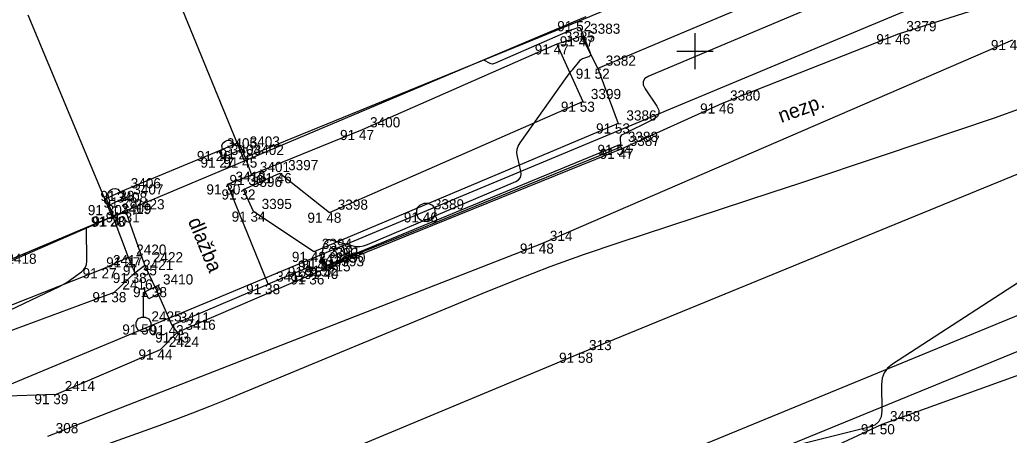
# Model space of a CAD drawing. Extents: x -711081 to -709338, y -1025122 to -1024092.
# Drawn here: x -710543.62 to -710516.33, y -1024835.58 to -1024824.13 of the extents above; entities that cross this region are included whole.
import ezdxf

# ---------------------------------------------------------------- set-up
doc = ezdxf.new("R2010")
doc.units = 0
for name, color, linetype in [('Ex_Minor Contours', 7, 'Continuous'), ('Z_betonova_konstrukce', 7, 'Continuous'), ('Z_body', 7, 'Continuous'), ('Z_body_cisla', 7, 'Continuous'), ('Z_body_vysky_redukovane', 7, 'Continuous'), ('Z_budova', 7, 'Continuous'), ('Z_hektometricka_sit', 7, 'Continuous'), ('Z_hrany_paty', 7, 'Continuous'), ('Z_katastr_hranice', 7, 'Continuous'), ('Z_katastr_hranice_katastralniho_uzemi', 7, 'Continuous'), ('Z_katastr_vnitrni_kresba', 7, 'Continuous'), ('Z_komunikace', 7, 'Continuous'), ('Z_komunikace_osa', 7, 'Continuous'), ('Z_obruba', 7, 'Continuous'), ('Z_ploty', 7, 'Continuous'), ('Z_ploty_znacky', 7, 'Continuous'), ('Z_popisy', 7, 'Continuous'), ('Z_rozhranni', 7, 'Continuous'), ('Z_site_kanalizace_znaky', 7, 'Continuous'), ('Z_site_vo_znaky', 7, 'Continuous'), ('Z_vstupy', 7, 'Continuous'), ('Z_zelen_obvod', 7, 'Continuous'), ('Z_zlabek', 7, 'Continuous')]:
    doc.layers.add(name, color=color, linetype=linetype)

# ---------------------------------------------------------------- blocks, each defined once
blk = doc.blocks.new('POINT_DISPLAY')
blk.add_line((0, 0), (0, 0))
blk = doc.blocks.new('Z216')
for p, q in [((-0.17, 0), (-0.15, 0.1)), ((-0.15, 0.1), (-0.1, 0.15)), ((-0.1, 0.15), (-0.03, 0.17)), ((-0.03, 0.17), (0.03, 0.17)), ((0.03, 0.17), (0.1, 0.15)), ((0.1, 0.15), (0.15, 0.1)), ((0.15, 0.1), (0.17, 0))]:
    blk.add_line(p, q)
blk = doc.blocks.new('Z13')
for p, q in [((0, 0.88), (0.45, 1.1)), ((0, 0.2), (0, 0.88)), ((0.15, 0.7), (0.05, 0.9)), ((0.5, 0.88), (0.15, 0.7)), ((0.4, 1.07), (0.5, 0.88)), ((-0.2, 0.05), (-0.15, 0.15)), ((-0.2, -0.05), (-0.2, 0.05)), ((-0.15, 0.15), (-0.05, 0.2)), ((-0.05, 0.2), (0.05, 0.2)), ((0.05, 0.2), (0.15, 0.15)), ((0.15, 0.15), (0.2, 0.05)), ((0.2, 0.05), (0.2, -0.05)), ((-0.15, -0.15), (-0.2, -0.05)), ((-0.05, -0.2), (-0.15, -0.15)), ((0.05, -0.2), (-0.05, -0.2)), ((0.15, -0.15), (0.05, -0.2)), ((0.2, -0.05), (0.15, -0.15))]:
    blk.add_line(p, q)
blk = doc.blocks.new('Z620')
for p, q in [((-0.25, 0.05), (-0.23, 0.13)), ((-0.25, -0.05), (-0.25, 0.05)), ((-0.23, 0.13), (-0.17, 0.2)), ((-0.17, 0.2), (-0.05, 0.25)), ((-0.05, 0.25), (0.05, 0.25)), ((0.05, 0.25), (0.17, 0.2)), ((0.17, 0.2), (0.23, 0.13)), ((0.23, 0.13), (0.25, 0.05)), ((0.25, 0.05), (0.25, -0.05)), ((-0.2, -0.17), (-0.25, -0.05)), ((-0.13, -0.23), (-0.2, -0.17)), ((-0.05, -0.25), (-0.13, -0.23)), ((0.05, -0.25), (-0.05, -0.25)), ((0.13, -0.23), (0.05, -0.25)), ((0.2, -0.17), (0.13, -0.23)), ((0.25, -0.05), (0.2, -0.17))]:
    blk.add_line(p, q)

msp = doc.modelspace()

# ---------------------------------------------------------------- linework, layer by layer
at = {"layer": 'Ex_Minor Contours'}
for points in [[(-710520.898, -1024823.422), (-710526.271, -1024825.688), (-710526.377, -1024825.752), (-710526.43, -1024825.832), (-710526.429, -1024825.927), (-710526.375, -1024826.039), (-710526.052, -1024826.516), (-710525.997, -1024826.628), (-710525.995, -1024826.727), (-710526.045, -1024826.811), (-710526.148, -1024826.882), (-710527.002, -1024827.306), (-710527.031, -1024827.326), (-710527.051, -1024827.35), (-710527.062, -1024827.38), (-710527.064, -1024827.416), (-710527.052, -1024827.567), (-710527.054, -1024827.602), (-710527.065, -1024827.631), (-710527.086, -1024827.654), (-710527.116, -1024827.672), (-710531.086, -1024829.291), (-710531.492, -1024829.456), (-710531.899, -1024829.621), (-710532.305, -1024829.785), (-710532.713, -1024829.948), (-710535.128, -1024830.914), (-710535.142, -1024830.917), (-710535.155, -1024830.917), (-710535.167, -1024830.912), (-710535.179, -1024830.904), (-710535.223, -1024830.861), (-710535.234, -1024830.85), (-710535.243, -1024830.839), (-710535.252, -1024830.827), (-710535.26, -1024830.814), (-710535.302, -1024830.745), (-710535.304, -1024830.741), (-710535.306, -1024830.736), (-710535.307, -1024830.732), (-710535.309, -1024830.727), (-710535.312, -1024830.708), (-710535.313, -1024830.704), (-710535.313, -1024830.699), (-710535.313, -1024830.694), (-710535.312, -1024830.69), (-710535.229, -1024830.335), (-710535.223, -1024830.316), (-710535.216, -1024830.299), (-710535.206, -1024830.283), (-710535.194, -1024830.268), (-710535.141, -1024830.209), (-710535.127, -1024830.197), (-710535.112, -1024830.19), (-710535.095, -1024830.188), (-710535.077, -1024830.19), (-710534.459, -1024830.36), (-710534.35, -1024830.381), (-710534.243, -1024830.383), (-710534.136, -1024830.366), (-710534.031, -1024830.331), (-710529.942, -1024828.592), (-710529.861, -1024828.543), (-710529.81, -1024828.48), (-710529.79, -1024828.401), (-710529.799, -1024828.307), (-710529.897, -1024827.9), (-710529.911, -1024827.801), (-710529.903, -1024827.705), (-710529.874, -1024827.614), (-710529.824, -1024827.527), (-710528.523, -1024825.702), (-710528.486, -1024825.651), (-710528.448, -1024825.601), (-710528.41, -1024825.552), (-710528.371, -1024825.503), (-710528.178, -1024825.268), (-710528.154, -1024825.242), (-710528.126, -1024825.221), (-710528.096, -1024825.203), (-710528.063, -1024825.19), (-710527.925, -1024825.146), (-710527.896, -1024825.132), (-710527.88, -1024825.113), (-710527.875, -1024825.087), (-710527.882, -1024825.057), (-710528.136, -1024824.405), (-710528.152, -1024824.377), (-710528.173, -1024824.36), (-710528.199, -1024824.355), (-710528.231, -1024824.36), (-710528.369, -1024824.404), (-710528.403, -1024824.415), (-710528.437, -1024824.428), (-710528.471, -1024824.441), (-710528.504, -1024824.455), (-710530.525, -1024825.343), (-710530.555, -1024825.353), (-710530.585, -1024825.355), (-710530.615, -1024825.351), (-710530.645, -1024825.339), (-710530.821, -1024825.244)], [(-710542.524, -1024836.3), (-710539.776, -1024835.318), (-710539.308, -1024835.147), (-710538.843, -1024834.971), (-710538.379, -1024834.789), (-710537.918, -1024834.601), (-710530.868, -1024831.675), (-710529.933, -1024831.298), (-710528.991, -1024830.938), (-710528.042, -1024830.596), (-710527.087, -1024830.273), (-710522.871, -1024828.889), (-710522.103, -1024828.636), (-710521.335, -1024828.381), (-710520.568, -1024828.125), (-710519.802, -1024827.867), (-710516.737, -1024826.833), (-710515.975, -1024826.564)], [(-710546.046, -1024833.16), (-710542.522, -1024831.483), (-710542.44, -1024831.442), (-710542.361, -1024831.398), (-710542.284, -1024831.349), (-710542.21, -1024831.297), (-710541.915, -1024831.08), (-710541.851, -1024831.021), (-710541.806, -1024830.953), (-710541.779, -1024830.876), (-710541.77, -1024830.789), (-710541.779, -1024829.876)], [(-710515.235, -1024830.831), (-710519.555, -1024833.627), (-710519.688, -1024833.737), (-710519.782, -1024833.867), (-710519.838, -1024834.017), (-710519.855, -1024834.189), (-710519.845, -1024834.916), (-710519.865, -1024835.081), (-710519.93, -1024835.211), (-710520.039, -1024835.307), (-710520.193, -1024835.368), (-710525.827, -1024836.766)]]:
    msp.add_lwpolyline(points, dxfattribs=at)
at = {"layer": 'Z_betonova_konstrukce'}
for p, q in [((-710541.05, -1024829.56), (-710540.63, -1024830.68)), ((-710540.69, -1024829.44), (-710541.04, -1024829.55)), ((-710540.17, -1024830.9), (-710540.69, -1024829.44)), ((-710540.63, -1024830.68), (-710540.45, -1024831.11)), ((-710540.45, -1024831.11), (-710540.17, -1024830.9))]:
    msp.add_line(p, q, dxfattribs=at)
at = {"layer": 'Z_budova'}
for p, q in [((-710521.51, -1024821.36), (-710528.19, -1024824.17)), ((-710528.19, -1024824.17), (-710537.4, -1024827.93)), ((-710537.6, -1024827.52), (-710537.5, -1024827.7)), ((-710537.4, -1024827.93), (-710537.5, -1024827.7)), ((-710541.24, -1024829.06), (-710541.16, -1024829.24)), ((-710541.16, -1024829.24), (-710541.04, -1024829.55)), ((-710544.21, -1024830.93), (-710541.05, -1024829.56)), ((-710541.05, -1024829.56), (-710541.04, -1024829.55))]:
    msp.add_line(p, q, dxfattribs=at)
at = {"layer": 'Z_hektometricka_sit'}
for p, q in [((-710525, -1024824.5), (-710525, -1024825.5)), ((-710525.5, -1024825), (-710524.5, -1024825))]:
    msp.add_line(p, q, dxfattribs=at)
at = {"layer": 'Z_hrany_paty'}
for p, q in [((-710541.28, -1024830.98), (-710540.63, -1024830.68)), ((-710547.74, -1024833.53), (-710541.28, -1024830.98)), ((-710541.01, -1024831.64), (-710540.45, -1024831.11)), ((-710544.83, -1024833.06), (-710541.01, -1024831.64))]:
    msp.add_line(p, q, dxfattribs=at)
at = {"layer": 'Z_katastr_hranice'}
for p, q in [((-710522.93, -1024836.07), (-710445.08, -1024804.13)), ((-710541.07, -1024829.56), (-710543.39, -1024824.01)), ((-710537.42, -1024828.02), (-710528, -1024824.04)), ((-710541.07, -1024829.56), (-710537.42, -1024828.02)), ((-710552.64, -1024834.41), (-710541.07, -1024829.56))]:
    msp.add_line(p, q, dxfattribs=at)
at = {"layer": 'Z_katastr_hranice_katastralniho_uzemi'}
msp.add_line((-710496.32, -1024814.35), (-710587.89, -1024852.54), dxfattribs=at)
msp.add_line((-710496.32, -1024814.35), (-710587.89, -1024852.54), dxfattribs=at)
at = {"layer": 'Z_katastr_vnitrni_kresba'}
msp.add_line((-710537.42, -1024828.02), (-710541.58, -1024817.88), dxfattribs=at)
at = {"layer": 'Z_komunikace'}
for p, q in [((-710529.22, -1024830.3), (-710516.23, -1024824.69)), ((-710542.85, -1024835.61), (-710529.22, -1024830.3)), ((-710526.42, -1024836.52), (-710513.3, -1024831.13))]:
    msp.add_line(p, q, dxfattribs=at)
at = {"layer": 'Z_komunikace_osa'}
for p, q in [((-710528.14, -1024833.31), (-710514.35, -1024827.67)), ((-710541.64, -1024838.94), (-710528.14, -1024833.31))]:
    msp.add_line(p, q, dxfattribs=at)
at = {"layer": 'Z_obruba'}
for p, q in [((-710527.08, -1024827.58), (-710535.15, -1024830.91)), ((-710527.08, -1024827.58), (-710527.02, -1024827.69)), ((-710535.29, -1024830.72), (-710535.34, -1024830.77)), ((-710535.15, -1024830.91), (-710535.29, -1024830.72))]:
    msp.add_line(p, q, dxfattribs=at)
at = {"layer": 'Z_ploty'}
for p, q in [((-710538.13, -1024827.75), (-710537.6, -1024827.52)), ((-710538.03, -1024827.93), (-710537.5, -1024827.7)), ((-710538.03, -1024827.93), (-710538.13, -1024827.75)), ((-710541.24, -1024829.06), (-710540.79, -1024828.85)), ((-710541.16, -1024829.24), (-710540.71, -1024829.03)), ((-710540.79, -1024828.85), (-710540.71, -1024829.03))]:
    msp.add_line(p, q, dxfattribs=at)
at = {"layer": 'Z_rozhranni'}
for p, q in [((-710518.62, -1024821.66), (-710527.68, -1024825.48)), ((-710514.69, -1024823.04), (-710519.39, -1024824.53)), ((-710528.12, -1024824.59), (-710528.81, -1024824.81)), ((-710527.68, -1024825.48), (-710528.12, -1024824.59)), ((-710519.39, -1024824.53), (-710524.25, -1024826.44)), ((-710528.81, -1024824.81), (-710534.18, -1024827.17)), ((-710524.25, -1024826.44), (-710527.02, -1024827.69)), ((-710534.18, -1024827.17), (-710537.23, -1024828.41)), ((-710527.02, -1024827.69), (-710535.19, -1024831)), ((-710537.4, -1024827.93), (-710537.23, -1024828.41)), ((-710537.89, -1024828.67), (-710537.23, -1024828.41)), ((-710536.77, -1024831.42), (-710537.89, -1024828.67)), ((-710539.89, -1024831.5), (-710540.17, -1024830.9)), ((-710535.19, -1024831), (-710535.55, -1024831.15)), ((-710535.34, -1024830.77), (-710535.19, -1024831)), ((-710539.89, -1024831.5), (-710539.43, -1024832.55)), ((-710539.43, -1024832.55), (-710536.77, -1024831.42)), ((-710539.74, -1024833.22), (-710539.28, -1024832.75)), ((-710542.61, -1024834.45), (-710539.74, -1024833.22)), ((-710519.84, -1024835.28), (-710514.91, -1024833.5)), ((-710547.25, -1024834.61), (-710542.61, -1024834.45)), ((-710525.29, -1024837.81), (-710519.84, -1024835.28))]:
    msp.add_line(p, q, dxfattribs=at)
at = {"layer": 'Z_vstupy'}
msp.add_line((-710540.79, -1024828.85), (-710538.13, -1024827.75), dxfattribs=at)
at = {"layer": 'Z_zelen_obvod'}
for p, q in [((-710528.81, -1024824.81), (-710528.09, -1024826.39)), ((-710527.68, -1024825.48), (-710527.12, -1024826.99)), ((-710535.08, -1024829.45), (-710528.09, -1024826.39)), ((-710527.12, -1024826.99), (-710535.51, -1024830.53)), ((-710537.45, -1024828.81), (-710536.45, -1024828.36)), ((-710536.45, -1024828.36), (-710535.08, -1024829.45)), ((-710537.17, -1024829.42), (-710537.45, -1024828.81)), ((-710535.51, -1024830.53), (-710537.17, -1024829.42))]:
    msp.add_line(p, q, dxfattribs=at)
at = {"layer": 'Z_zlabek'}
for p, q in [((-710535.62, -1024830.94), (-710536.77, -1024831.42)), ((-710535.62, -1024830.94), (-710535.55, -1024831.15)), ((-710535.55, -1024831.15), (-710539.28, -1024832.75)), ((-710539.43, -1024832.55), (-710539.28, -1024832.75))]:
    msp.add_line(p, q, dxfattribs=at)

# ---------------------------------------------------------------- block references
at = {"layer": 'Z_body'}
for p in [(-710528.19, -1024824.17), (-710528.12, -1024824.59), (-710519.39, -1024824.53), (-710528.81, -1024824.81), (-710527.68, -1024825.48), (-710528.09, -1024826.39), (-710524.25, -1024826.44), (-710534.18, -1024827.17), (-710527.12, -1024826.99), (-710537.5, -1024827.7), (-710527.08, -1024827.58), (-710527.02, -1024827.69), (-710538.13, -1024827.75), (-710538.03, -1024827.93), (-710537.4, -1024827.93), (-710537.23, -1024828.41), (-710536.45, -1024828.36), (-710537.89, -1024828.67), (-710537.45, -1024828.81), (-710540.79, -1024828.85), (-710540.71, -1024829.03), (-710541.16, -1024829.24), (-710541.05, -1024829.56), (-710541.04, -1024829.55), (-710540.69, -1024829.44), (-710537.17, -1024829.42), (-710535.08, -1024829.45), (-710532.42, -1024829.44), (-710529.22, -1024830.3), (-710540.63, -1024830.68), (-710535.51, -1024830.53), (-710535.29, -1024830.72), (-710541.28, -1024830.98), (-710540.17, -1024830.9), (-710535.62, -1024830.94), (-710535.34, -1024830.77), (-710535.19, -1024831), (-710535.15, -1024830.91), (-710540.45, -1024831.11), (-710535.55, -1024831.15), (-710539.89, -1024831.5), (-710536.77, -1024831.42), (-710541.01, -1024831.64), (-710540.21, -1024832.53), (-710539.43, -1024832.55), (-710539.28, -1024832.75), (-710539.74, -1024833.22), (-710528.14, -1024833.31), (-710542.61, -1024834.45), (-710519.84, -1024835.28)]:
    msp.add_blockref('POINT_DISPLAY', p, dxfattribs=at)
at = {"layer": 'Z_ploty_znacky'}
for p, rotation in [((-710537.87, -1024827.63), 23.5), ((-710541.01, -1024828.96), 25)]:
    msp.add_blockref('Z216', p, dxfattribs=dict(at, rotation=rotation))
at = {"layer": 'Z_site_kanalizace_znaky'}
msp.add_blockref('Z620', (-710532.42, -1024829.44), dxfattribs=at)
at = {"layer": 'Z_site_vo_znaky'}
msp.add_blockref('Z13', (-710540.21, -1024832.53), dxfattribs=at)

# ---------------------------------------------------------------- texts
at = {"layer": 'Z_body_cisla'}
for s, p in [('3379', (-710519.17, -1024824.45)), ('3385', (-710528.59, -1024824.74)), ('3383', (-710527.89, -1024824.52)), ('3382', (-710527.46, -1024825.4)), ('3399', (-710527.87, -1024826.32)), ('3380', (-710524.03, -1024826.36)), ('3386', (-710526.89, -1024826.91)), ('3400', (-710533.96, -1024827.1)), ('3405', (-710537.91, -1024827.68)), ('3403', (-710537.28, -1024827.63)), ('3388', (-710526.85, -1024827.5)), ('3387', (-710526.8, -1024827.61)), ('3404', (-710537.8, -1024827.86)), ('3402', (-710537.17, -1024827.86)), ('3397', (-710536.22, -1024828.28)), ('3401', (-710537, -1024828.33)), ('3406', (-710540.56, -1024828.78)), ('3413', (-710537.67, -1024828.6)), ('3396', (-710537.22, -1024828.74)), ('3407', (-710540.49, -1024828.95)), ('3408', (-710540.94, -1024829.17)), ('2423', (-710540.46, -1024829.36)), ('3395', (-710536.95, -1024829.35)), ('3398', (-710534.85, -1024829.37)), ('3389', (-710532.2, -1024829.36)), ('2419', (-710540.83, -1024829.49)), ('3409', (-710540.82, -1024829.48)), ('3394', (-710535.29, -1024830.45)), ('314', (-710529, -1024830.23)), ('2420', (-710540.41, -1024830.61)), ('3392', (-710535.12, -1024830.7)), ('3391', (-710535.06, -1024830.65)), ('2418', (-710543.99, -1024830.86)), ('2417', (-710541.05, -1024830.9)), ('2421', (-710540.22, -1024831.03)), ('2422', (-710539.95, -1024830.82)), ('3414', (-710535.39, -1024830.86)), ('3393', (-710534.96, -1024830.93)), ('3390', (-710534.92, -1024830.83)), ('3415', (-710535.33, -1024831.07)), ('2416', (-710540.79, -1024831.57)), ('3410', (-710539.67, -1024831.43)), ('3412', (-710536.55, -1024831.35)), ('2425', (-710539.99, -1024832.45)), ('3411', (-710539.21, -1024832.48)), ('3416', (-710539.05, -1024832.68)), ('2424', (-710539.51, -1024833.15)), ('313', (-710527.92, -1024833.24)), ('2414', (-710542.38, -1024834.37)), ('3458', (-710519.62, -1024835.2)), ('308', (-710542.63, -1024835.53))]:
    msp.add_text(s, height=0.28, dxfattribs=at).set_placement(p)
at = {"layer": 'Z_body_vysky_redukovane'}
for s, p in [('91 52', (-710528.797, -1024824.45)), ('91 47', (-710528.727, -1024824.87)), ('91 46', (-710519.997, -1024824.81)), ('91 44', (-710516.837, -1024824.97)), ('91 47', (-710529.417, -1024825.09)), ('91 52', (-710528.287, -1024825.76)), ('91 53', (-710528.697, -1024826.67)), ('91 46', (-710524.857, -1024826.72)), ('91 47', (-710534.787, -1024827.45)), ('91 53', (-710527.727, -1024827.27)), ('91 26', (-710538.737, -1024828.03)), ('91 28', (-710538.107, -1024827.98)), ('91 54', (-710527.687, -1024827.86)), ('91 47', (-710527.627, -1024827.97)), ('91 27', (-710538.637, -1024828.21)), ('91 45', (-710538.007, -1024828.21)), ('91 36', (-710537.837, -1024828.69)), ('91 46', (-710537.057, -1024828.64)), ('91 30', (-710538.473, -1024828.95)), ('91 32', (-710538.057, -1024829.09)), ('91 28', (-710541.397, -1024829.13)), ('91 28', (-710541.317, -1024829.31)), ('91 30', (-710541.743, -1024829.52)), ('91 28', (-710541.657, -1024829.84)), ('91 30', (-710541.623, -1024829.83)), ('91 31', (-710541.25, -1024829.72)), ('91 34', (-710537.777, -1024829.7)), ('91 48', (-710535.687, -1024829.73)), ('91 46', (-710533.027, -1024829.72)), ('91 48', (-710529.827, -1024830.58)), ('91 27', (-710541.237, -1024830.96)), ('91 42', (-710536.117, -1024830.81)), ('91 51', (-710535.85, -1024831)), ('91 27', (-710541.887, -1024831.26)), ('91 35', (-710540.777, -1024831.18)), ('91 36', (-710536.227, -1024831.22)), ('91 48', (-710535.947, -1024831.05)), ('91 40', (-710535.773, -1024831.28)), ('91 52', (-710535.757, -1024831.19)), ('91 38', (-710541.057, -1024831.39)), ('91 36', (-710536.157, -1024831.43)), ('91 38', (-710540.497, -1024831.78)), ('91 38', (-710537.377, -1024831.7)), ('91 38', (-710541.617, -1024831.92)), ('91 50', (-710540.793, -1024832.81)), ('91 43', (-710540.037, -1024832.83)), ('91 43', (-710539.887, -1024833.03)), ('91 44', (-710540.347, -1024833.5)), ('91 58', (-710528.747, -1024833.59)), ('91 39', (-710543.217, -1024834.73)), ('91 50', (-710520.423, -1024835.56))]:
    msp.add_text(s, height=0.28, dxfattribs=at).set_placement(p)
at = {"layer": 'Z_popisy'}
for s, rotation, p in [('nezp.', 19.8, (-710522.62, -1024826.98)), ('dlažba', 292.5, (-710538.99, -1024829.68))]:
    msp.add_text(s, height=0.4, rotation=rotation, dxfattribs=at).set_placement(p)

doc.saveas('drawing.dxf')
